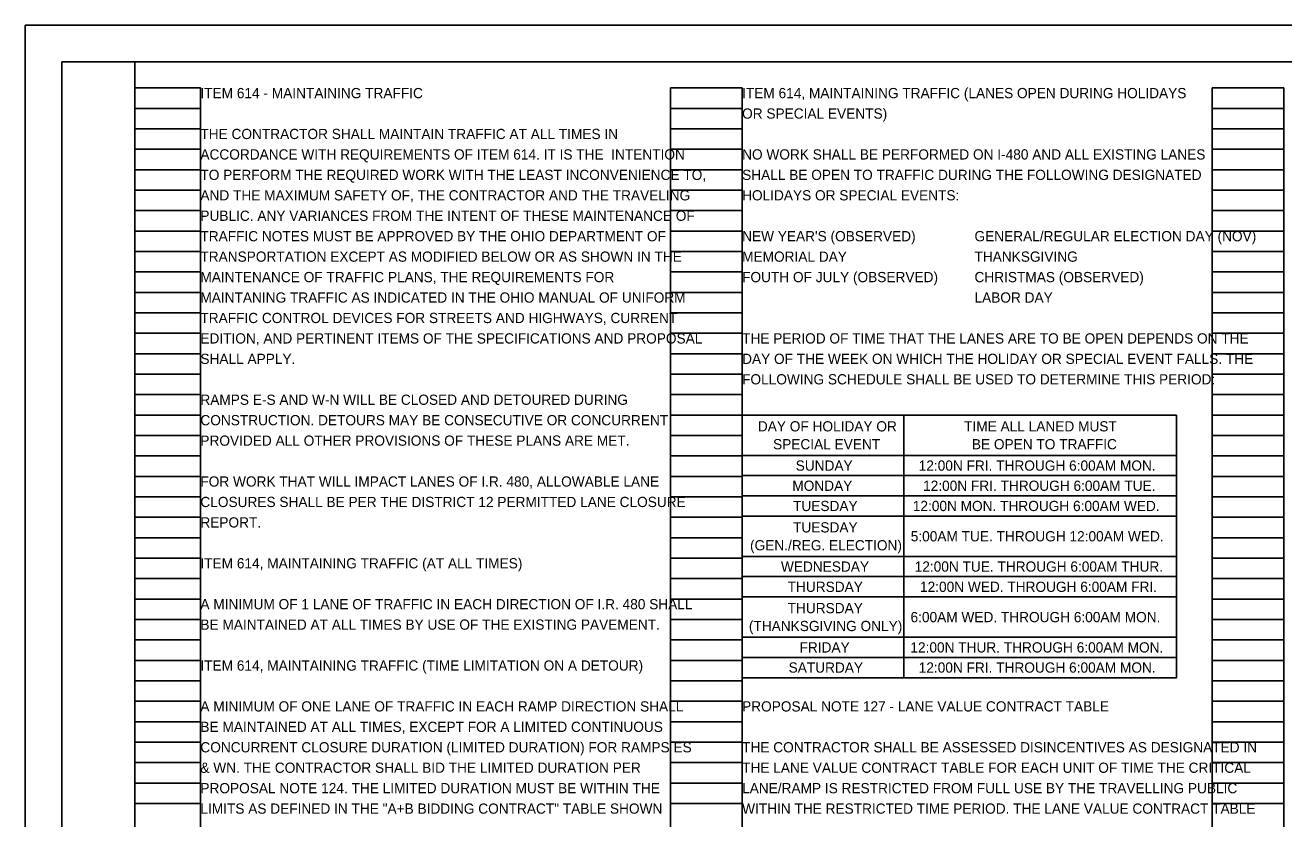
# Model space of a CAD drawing. Extents: x 0 to 34, y -9.1 to 22.
# Drawn here: x 0 to 17.24, y 11.13 to 22 of the extents above; entities that cross this region are included whole.
import ezdxf

# ---------------------------------------------------------------- set-up
doc = ezdxf.new("R2010")
doc.units = 0
for name, color, linetype in [('SH_Border', 7, 'Continuous'), ('SH_Cut_Line', 7, 'Continuous'), ('SH_Data', 7, 'Continuous'), ('SH_Text', 7, 'Continuous')]:
    doc.layers.add(name, color=color, linetype=linetype)

msp = doc.modelspace()

# ---------------------------------------------------------------- linework, layer by layer
at = {"layer": 'SH_Border'}
for points in [[(0.5, 21.5), (1.5, 21.5), (1.5, 0.5), (0.5, 0.5)], [(1.5, 21.5), (33.5, 21.5), (33.5, 0.5), (1.5, 0.5)]]:
    msp.add_lwpolyline(points, close=True, dxfattribs=at)
at = {"layer": 'SH_Cut_Line'}
msp.add_lwpolyline([(0, 0), (34, 0), (34, 22), (0, 22)], close=True, dxfattribs=at)
at = {"layer": 'SH_Data'}
for p, q in [((1.5, 0.98), (1.5, 21.14)), ((1.5, 21.14), (2.4, 21.14)), ((2.4, 0.98), (2.4, 21.14)), ((8.84, 0.98), (8.84, 21.14)), ((8.84, 21.14), (9.82, 21.14)), ((9.82, 0.98), (9.82, 21.14)), ((16.26, 0.98), (16.26, 21.14)), ((16.26, 21.14), (17.24, 21.14)), ((17.24, 0.98), (17.24, 21.14)), ((1.5, 20.86), (2.4, 20.86)), ((8.84, 20.86), (9.82, 20.86)), ((16.26, 20.86), (17.24, 20.86)), ((1.5, 20.58), (2.4, 20.58)), ((8.84, 20.58), (9.82, 20.58)), ((16.26, 20.58), (17.24, 20.58)), ((1.5, 20.3), (2.4, 20.3)), ((8.84, 20.3), (9.82, 20.3)), ((16.26, 20.3), (17.24, 20.3)), ((1.5, 20.02), (2.4, 20.02)), ((8.84, 20.02), (9.82, 20.02)), ((16.26, 20.02), (17.24, 20.02)), ((1.5, 19.74), (2.4, 19.74)), ((8.84, 19.74), (9.82, 19.74)), ((16.26, 19.74), (17.24, 19.74)), ((1.5, 19.46), (2.4, 19.46)), ((8.84, 19.46), (9.82, 19.46)), ((16.26, 19.46), (17.24, 19.46)), ((1.5, 19.18), (2.4, 19.18)), ((8.84, 19.18), (9.82, 19.18)), ((16.26, 19.18), (17.24, 19.18)), ((1.5, 18.9), (2.4, 18.9)), ((8.84, 18.9), (9.82, 18.9)), ((16.26, 18.9), (17.24, 18.9)), ((1.5, 18.62), (2.4, 18.62)), ((8.84, 18.62), (9.82, 18.62)), ((16.26, 18.62), (17.24, 18.62)), ((1.5, 18.34), (2.4, 18.34)), ((8.84, 18.34), (9.82, 18.34)), ((16.26, 18.34), (17.24, 18.34)), ((1.5, 18.06), (2.4, 18.06)), ((8.84, 18.06), (9.82, 18.06)), ((16.26, 18.06), (17.24, 18.06)), ((1.5, 17.78), (2.4, 17.78)), ((8.84, 17.78), (9.82, 17.78)), ((16.26, 17.78), (17.24, 17.78)), ((1.5, 17.5), (2.4, 17.5)), ((8.84, 17.5), (9.82, 17.5)), ((16.26, 17.5), (17.24, 17.5)), ((1.5, 17.22), (2.4, 17.22)), ((8.84, 17.22), (9.82, 17.22)), ((16.26, 17.22), (17.24, 17.22)), ((1.5, 16.94), (2.4, 16.94)), ((8.84, 16.94), (9.82, 16.94)), ((16.26, 16.94), (17.24, 16.94)), ((1.5, 16.66), (2.4, 16.66)), ((8.84, 16.66), (9.82, 16.66)), ((16.26, 16.66), (17.24, 16.66)), ((1.5, 16.38), (2.4, 16.38)), ((8.84, 16.38), (9.82, 16.38)), ((16.26, 16.38), (17.24, 16.38)), ((1.5, 16.1), (2.4, 16.1)), ((8.84, 16.1), (9.82, 16.1)), ((16.26, 16.1), (17.24, 16.1)), ((1.5, 15.82), (2.4, 15.82)), ((8.84, 15.82), (9.82, 15.82)), ((16.26, 15.82), (17.24, 15.82)), ((1.5, 15.54), (2.4, 15.54)), ((8.84, 15.54), (9.82, 15.54)), ((16.26, 15.54), (17.24, 15.54)), ((1.5, 15.26), (2.4, 15.26)), ((8.84, 15.26), (9.82, 15.26)), ((16.26, 15.26), (17.24, 15.26)), ((1.5, 14.98), (2.4, 14.98)), ((8.84, 14.98), (9.82, 14.98)), ((16.26, 14.98), (17.24, 14.98)), ((1.5, 14.7), (2.4, 14.7)), ((8.84, 14.7), (9.82, 14.7)), ((16.26, 14.7), (17.24, 14.7)), ((1.5, 14.42), (2.4, 14.42)), ((8.84, 14.42), (9.82, 14.42)), ((16.26, 14.42), (17.24, 14.42)), ((1.5, 14.14), (2.4, 14.14)), ((8.84, 14.14), (9.82, 14.14)), ((16.26, 14.14), (17.24, 14.14)), ((1.5, 13.86), (2.4, 13.86)), ((8.84, 13.86), (9.82, 13.86)), ((16.26, 13.86), (17.24, 13.86)), ((1.5, 13.58), (2.4, 13.58)), ((8.84, 13.58), (9.82, 13.58)), ((16.26, 13.58), (17.24, 13.58)), ((1.5, 13.3), (2.4, 13.3)), ((8.84, 13.3), (9.82, 13.3)), ((16.26, 13.3), (17.24, 13.3)), ((1.5, 13.02), (2.4, 13.02)), ((8.84, 13.02), (9.82, 13.02)), ((16.26, 13.02), (17.24, 13.02)), ((1.5, 12.74), (2.4, 12.74)), ((8.84, 12.74), (9.82, 12.74)), ((16.26, 12.74), (17.24, 12.74)), ((1.5, 12.46), (2.4, 12.46)), ((8.84, 12.46), (9.82, 12.46)), ((16.26, 12.46), (17.24, 12.46)), ((1.5, 12.18), (2.4, 12.18)), ((8.84, 12.18), (9.82, 12.18)), ((16.26, 12.18), (17.24, 12.18)), ((1.5, 11.9), (2.4, 11.9)), ((8.84, 11.9), (9.82, 11.9)), ((16.26, 11.9), (17.24, 11.9)), ((1.5, 11.62), (2.4, 11.62)), ((8.84, 11.62), (9.82, 11.62)), ((16.26, 11.62), (17.24, 11.62)), ((1.5, 11.34), (2.4, 11.34)), ((8.84, 11.34), (9.82, 11.34)), ((16.26, 11.34), (17.24, 11.34))]:
    msp.add_line(p, q, dxfattribs=at)
at = {"layer": 'SH_Text'}
for p, q in [((9.82, 16.66), (15.769, 16.66)), ((9.82, 16.66), (9.82, 13.063)), ((12.033, 16.66), (12.033, 13.063)), ((15.769, 16.66), (15.769, 13.063)), ((9.82, 16.107), (15.769, 16.107)), ((9.82, 15.83), (15.769, 15.83)), ((9.82, 15.553), (15.769, 15.553)), ((9.82, 15.277), (15.769, 15.277)), ((9.82, 14.723), (15.769, 14.723)), ((9.82, 14.447), (15.769, 14.447)), ((9.82, 14.17), (15.769, 14.17)), ((9.82, 13.617), (15.769, 13.617)), ((9.82, 13.34), (15.769, 13.34)), ((9.82, 13.063), (15.769, 13.063))]:
    msp.add_line(p, q, dxfattribs=at)

# ---------------------------------------------------------------- texts
for s, p in [('ITEM 614 - MAINTAINING TRAFFIC', (2.4, 21)), ('ITEM 614, MAINTAINING TRAFFIC (LANES OPEN DURING HOLIDAYS', (9.82, 21)), ('OR SPECIAL EVENTS)', (9.82, 20.72)), ('THE CONTRACTOR SHALL MAINTAIN TRAFFIC AT ALL TIMES IN ', (2.4, 20.44)), ('ACCORDANCE WITH REQUIREMENTS OF ITEM 614. IT IS THE  INTENTION ', (2.4, 20.16)), ('NO WORK SHALL BE PERFORMED ON I-480 AND ALL EXISTING LANES ', (9.82, 20.16)), ('TO PERFORM THE REQUIRED WORK WITH THE LEAST INCONVENIENCE TO, ', (2.4, 19.88)), ('SHALL BE OPEN TO TRAFFIC DURING THE FOLLOWING DESIGNATED ', (9.82, 19.88)), ('AND THE MAXIMUM SAFETY OF, THE CONTRACTOR AND THE TRAVELING ', (2.4, 19.6)), ('HOLIDAYS OR SPECIAL EVENTS:', (9.82, 19.6)), ('PUBLIC. ANY VARIANCES FROM THE INTENT OF THESE MAINTENANCE OF ', (2.4, 19.32)), ('TRAFFIC NOTES MUST BE APPROVED BY THE OHIO DEPARTMENT OF ', (2.4, 19.04)), ("NEW YEAR'S (OBSERVED)", (9.82, 19.04)), ('GENERAL/REGULAR ELECTION DAY (NOV)', (13.003, 19.04)), ('TRANSPORTATION EXCEPT AS MODIFIED BELOW OR AS SHOWN IN THE ', (2.4, 18.76)), ('MEMORIAL DAY', (9.82, 18.76)), ('THANKSGIVING', (13.003, 18.76)), ('MAINTENANCE OF TRAFFIC PLANS, THE REQUIREMENTS FOR ', (2.4, 18.48)), ('FOUTH OF JULY (OBSERVED)', (9.82, 18.48)), ('CHRISTMAS (OBSERVED)', (13.003, 18.48)), ('MAINTANING TRAFFIC AS INDICATED IN THE OHIO MANUAL OF UNIFORM ', (2.4, 18.2)), ('LABOR DAY', (13.003, 18.2)), ('TRAFFIC CONTROL DEVICES FOR STREETS AND HIGHWAYS, CURRENT ', (2.4, 17.92)), ('EDITION, AND PERTINENT ITEMS OF THE SPECIFICATIONS AND PROPOSAL ', (2.4, 17.64)), ('THE PERIOD OF TIME THAT THE LANES ARE TO BE OPEN DEPENDS ON THE ', (9.82, 17.64)), ('SHALL APPLY.', (2.4, 17.36)), ('DAY OF THE WEEK ON WHICH THE HOLIDAY OR SPECIAL EVENT FALLS. THE ', (9.82, 17.36)), ('FOLLOWING SCHEDULE SHALL BE USED TO DETERMINE THIS PERIOD:', (9.82, 17.08)), ('RAMPS E-S AND W-N WILL BE CLOSED AND DETOURED DURING ', (2.4, 16.8)), ('CONSTRUCTION. DETOURS MAY BE CONSECUTIVE OR CONCURRENT', (2.4, 16.52)), ('DAY OF HOLIDAY OR', (10.036, 16.436)), ('TIME ALL LANED MUST ', (12.861, 16.436)), ('PROVIDED ALL OTHER PROVISIONS OF THESE PLANS ARE MET. ', (2.4, 16.24)), ('SPECIAL EVENT', (10.244, 16.191)), ('BE OPEN TO TRAFFIC', (12.967, 16.191)), ('SUNDAY', (10.554, 15.898)), ('12:00N FRI. THROUGH 6:00AM MON.', (12.239, 15.898)), ('FOR WORK THAT WILL IMPACT LANES OF I.R. 480, ALLOWABLE LANE ', (2.4, 15.68)), ('MONDAY', (10.508, 15.622)), ('12:00N FRI. THROUGH 6:00AM TUE.', (12.299, 15.622)), ('CLOSURES SHALL BE PER THE DISTRICT 12 PERMITTED LANE CLOSURE ', (2.4, 15.4)), ('TUESDAY', (10.518, 15.345)), ('12:00N MON. THROUGH 6:00AM WED.', (12.158, 15.345)), ('REPORT.   ', (2.4, 15.12)), ('TUESDAY', (10.518, 15.052)), ('5:00AM TUE. THROUGH 12:00AM WED.', (12.13, 14.93)), ('(GEN./REG. ELECTION)', (9.929, 14.807)), ('ITEM 614, MAINTAINING TRAFFIC (AT ALL TIMES)', (2.4, 14.56)), ('WEDNESDAY', (10.352, 14.515)), ('12:00N TUE. THROUGH 6:00AM THUR.', (12.184, 14.515)), ('THURSDAY', (10.444, 14.238)), ('12:00N WED. THROUGH 6:00AM FRI.', (12.257, 14.238)), ('A MINIMUM OF 1 LANE OF TRAFFIC IN EACH DIRECTION OF I.R. 480 SHALL ', (2.4, 14)), ('THURSDAY', (10.444, 13.946)), ('6:00AM WED. THROUGH 6:00AM MON.', (12.127, 13.823)), ('BE MAINTAINED AT ALL TIMES BY USE OF THE EXISTING PAVEMENT.', (2.4, 13.72)), ('(THANKSGIVING ONLY)', (9.913, 13.701)), ('FRIDAY', (10.607, 13.408)), ('12:00N THUR. THROUGH 6:00AM MON.', (12.125, 13.408)), ('ITEM 614, MAINTAINING TRAFFIC (TIME LIMITATION ON A DETOUR)', (2.4, 13.16)), ('SATURDAY', (10.457, 13.132)), ('12:00N FRI. THROUGH 6:00AM MON.', (12.239, 13.132)), ('A MINIMUM OF ONE LANE OF TRAFFIC IN EACH RAMP DIRECTION SHALL ', (2.4, 12.6)), ('PROPOSAL NOTE 127 - LANE VALUE CONTRACT TABLE', (9.82, 12.6)), ('BE MAINTAINED AT ALL TIMES, EXCEPT FOR A LIMITED CONTINUOUS ', (2.4, 12.32)), ('CONCURRENT CLOSURE DURATION (LIMITED DURATION) FOR RAMPS ES ', (2.4, 12.04)), ('THE CONTRACTOR SHALL BE ASSESSED DISINCENTIVES AS DESIGNATED IN ', (9.82, 12.04)), ('& WN. THE CONTRACTOR SHALL BID THE LIMITED DURATION PER ', (2.4, 11.76)), ('THE LANE VALUE CONTRACT TABLE FOR EACH UNIT OF TIME THE CRITICAL ', (9.82, 11.76)), ('PROPOSAL NOTE 124. THE LIMITED DURATION MUST BE WITHIN THE ', (2.4, 11.48)), ('LANE/RAMP IS RESTRICTED FROM FULL USE BY THE TRAVELLING PUBLIC ', (9.82, 11.48)), ('LIMITS AS DEFINED IN THE "A+B BIDDING CONTRACT" TABLE SHOWN ', (2.4, 11.2)), ('WITHIN THE RESTRICTED TIME PERIOD. THE LANE VALUE CONTRACT TABLE ', (9.82, 11.2))]:
    msp.add_text(s, height=0.14, dxfattribs=at).set_placement(p)

doc.saveas('drawing.dxf')
